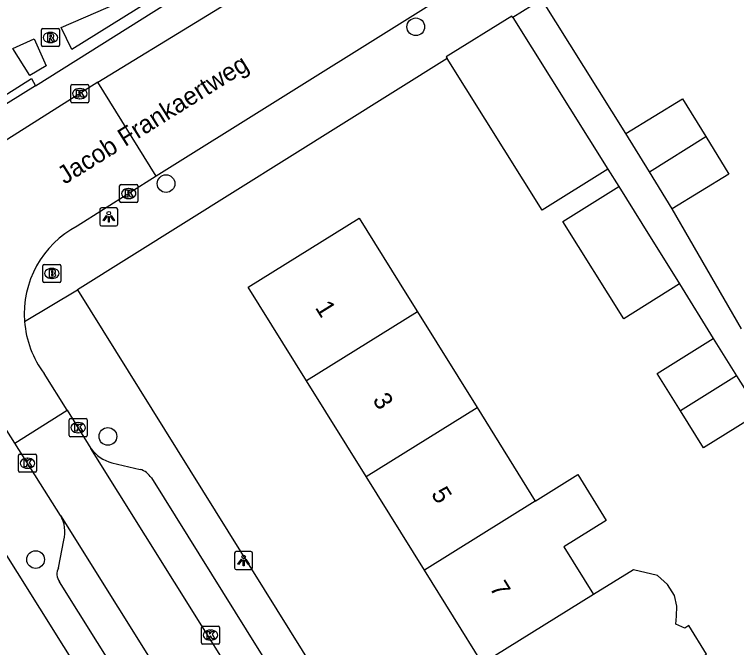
# Model space of a CAD drawing. Extents: x 159353 to 160616, y 385893 to 387321.
# Drawn here: x 159682.19 to 159722.15, y 386153.33 to 386188.38 of the extents above; entities that cross this region are included whole.
import ezdxf

# ---------------------------------------------------------------- set-up
doc = ezdxf.new("R2010")
doc.units = 0
for name, color, linetype in [('IMGEO_Boom', 7, 'Continuous'), ('IMGEO_Brandkraan', 7, 'Continuous'), ('IMGEO_Kolk', 7, 'Continuous'), ('IMGEO_Lichtpunt', 7, 'Continuous'), ('IMGEO_Openbare_ruimte_label', 7, 'Continuous'), ('IMGEO_Pand', 7, 'Continuous'), ('IMGEO_Pand_nummerreeks', 7, 'Continuous'), ('IMGEO_Rijbaan_lokaal_open', 7, 'Continuous'), ('IMGEO_Rioolput', 7, 'Continuous'), ('IMGEO_Voetpad_open', 7, 'Continuous')]:
    doc.layers.add(name, color=color, linetype=linetype)

msp = doc.modelspace()

# ---------------------------------------------------------------- linework, layer by layer
at = {"layer": 'IMGEO_Boom'}
for centre in [(159704.397, 386187.696), (159690.577, 386179.013), (159687.358, 386165.017), (159683.361, 386158.199)]:
    msp.add_circle(centre, 0.489, dxfattribs=at)
at = {"layer": 'IMGEO_Brandkraan'}
for p, q in [((159683.835, 386174.543), (159684.687, 386174.543)), ((159683.76, 386173.617), (159683.76, 386174.469)), ((159684.248, 386174.323), (159684.273, 386174.323)), ((159684.761, 386174.469), (159684.761, 386173.617)), ((159684.271, 386173.763), (159684.246, 386173.763)), ((159684.687, 386173.543), (159683.835, 386173.543))]:
    msp.add_line(p, q, dxfattribs=at)
for points in [[(159683.835, 386174.543), (159684.687, 386174.543)], [(159683.76, 386173.617), (159683.76, 386174.469)], [(159684.108, 386174.243), (159684.108, 386173.843), (159684.321, 386173.843)], [(159684.339, 386174.243), (159684.108, 386174.243)], [(159684.287, 386174.162), (159684.233, 386174.162), (159684.233, 386174.086)], [(159684.761, 386174.469), (159684.761, 386173.617)], [(159684.233, 386174.086), (159684.286, 386174.086)], [(159684.295, 386174.01), (159684.233, 386174.01), (159684.233, 386173.929)], [(159684.233, 386173.929), (159684.295, 386173.929)], [(159684.687, 386173.543), (159683.835, 386173.543)]]:
    msp.add_lwpolyline(points, dxfattribs=at)
for centre, radius, start, end in [((159683.837, 386174.467), 0.0765, 91.552, 178.448), ((159683.837, 386174.467), 0.0765, 91.552, 178.448), ((159684.685, 386174.467), 0.0765, 1.552, 88.448), ((159684.685, 386174.467), 0.0765, 1.552, 88.448), ((159684.288, 386174.124), 0.0379, 267.8285, 90.9355), ((159684.343, 386174.098), 0.145, 59.4692, 91.5367), ((159684.368, 386174.145), 0.0922, 285.5137, 58.1501), ((159684.296, 386173.969), 0.0404, 269.8759, 90.5077), ((159684.327, 386174.094), 0.251, 268.6676, 293.5347), ((159684.373, 386173.953), 0.105, 301.3115, 78.989), ((159683.837, 386173.619), 0.0765, 181.552, 268.448), ((159683.837, 386173.619), 0.0765, 181.552, 268.448), ((159684.685, 386173.619), 0.0765, 271.552, 358.448), ((159684.685, 386173.619), 0.0765, 271.552, 358.448)]:
    msp.add_arc(centre, radius, start, end, dxfattribs=at)
for centre, major_axis, ratio, start_param, end_param in [((159684.247, 386174.043), (-0.387, 0.002), 0.722429, 4.712389, 7.853982), ((159684.272, 386174.043), (-0.39, 0.002), 0.717154, 1.570796, 4.712389)]:
    msp.add_ellipse(centre, major_axis=major_axis, ratio=ratio, start_param=start_param, end_param=end_param, dxfattribs=at)
at = {"layer": 'IMGEO_Kolk'}
for p, q in [((159685.304, 386183.569), (159685.304, 386184.421)), ((159685.379, 386184.495), (159686.231, 386184.495)), ((159685.792, 386184.275), (159685.817, 386184.275)), ((159686.305, 386184.421), (159686.305, 386183.569)), ((159686.231, 386183.495), (159685.379, 386183.495)), ((159685.815, 386183.715), (159685.79, 386183.715)), ((159688.085, 386178.963), (159688.937, 386178.963)), ((159688.01, 386178.037), (159688.01, 386178.889)), ((159688.498, 386178.743), (159688.523, 386178.743)), ((159689.011, 386178.889), (159689.011, 386178.037)), ((159688.521, 386178.183), (159688.496, 386178.183)), ((159688.937, 386177.963), (159688.085, 386177.963)), ((159685.214, 386165.077), (159685.214, 386165.929)), ((159685.289, 386166.003), (159686.141, 386166.003)), ((159685.702, 386165.783), (159685.727, 386165.783)), ((159686.215, 386165.929), (159686.215, 386165.077)), ((159686.141, 386165.003), (159685.289, 386165.003)), ((159685.725, 386165.223), (159685.7, 386165.223)), ((159682.408, 386163.107), (159682.408, 386163.959)), ((159682.483, 386164.033), (159683.335, 386164.033)), ((159682.896, 386163.813), (159682.921, 386163.813)), ((159683.409, 386163.959), (159683.409, 386163.107)), ((159683.335, 386163.033), (159682.483, 386163.033)), ((159682.919, 386163.253), (159682.894, 386163.253)), ((159692.537, 386153.591), (159692.537, 386154.443)), ((159692.612, 386154.517), (159693.464, 386154.517)), ((159693.025, 386154.297), (159693.05, 386154.297)), ((159693.538, 386154.443), (159693.538, 386153.591)), ((159693.464, 386153.517), (159692.612, 386153.517)), ((159693.048, 386153.737), (159693.023, 386153.737))]:
    msp.add_line(p, q, dxfattribs=at)
for points in [[(159685.304, 386183.569), (159685.304, 386184.421)], [(159685.379, 386184.495), (159686.231, 386184.495)], [(159685.625, 386184.195), (159685.748, 386184.195), (159685.748, 386184.044), (159685.878, 386184.195), (159686.042, 386184.195), (159685.896, 386184.044), (159686.049, 386183.795), (159685.897, 386183.795), (159685.812, 386183.959), (159685.748, 386183.892), (159685.748, 386183.795), (159685.625, 386183.795), (159685.625, 386184.195)], [(159686.305, 386184.421), (159686.305, 386183.569)], [(159686.231, 386183.495), (159685.379, 386183.495)], [(159688.085, 386178.963), (159688.937, 386178.963)], [(159688.01, 386178.037), (159688.01, 386178.889)], [(159688.331, 386178.663), (159688.454, 386178.663), (159688.454, 386178.512), (159688.584, 386178.663), (159688.748, 386178.663), (159688.602, 386178.512), (159688.755, 386178.263), (159688.603, 386178.263), (159688.518, 386178.427), (159688.454, 386178.36), (159688.454, 386178.263), (159688.331, 386178.263), (159688.331, 386178.663)], [(159689.011, 386178.889), (159689.011, 386178.037)], [(159688.937, 386177.963), (159688.085, 386177.963)], [(159685.214, 386165.077), (159685.214, 386165.929)], [(159685.289, 386166.003), (159686.141, 386166.003)], [(159686.215, 386165.929), (159686.215, 386165.077)], [(159685.535, 386165.703), (159685.658, 386165.703), (159685.658, 386165.552), (159685.788, 386165.703), (159685.952, 386165.703), (159685.806, 386165.552), (159685.959, 386165.303), (159685.807, 386165.303), (159685.722, 386165.467), (159685.658, 386165.4), (159685.658, 386165.303), (159685.535, 386165.303), (159685.535, 386165.703)], [(159686.141, 386165.003), (159685.289, 386165.003)], [(159682.408, 386163.107), (159682.408, 386163.959)], [(159682.483, 386164.033), (159683.335, 386164.033)], [(159683.409, 386163.959), (159683.409, 386163.107)], [(159682.729, 386163.733), (159682.852, 386163.733), (159682.852, 386163.582), (159682.982, 386163.733), (159683.146, 386163.733), (159683, 386163.582), (159683.153, 386163.333), (159683.001, 386163.333), (159682.916, 386163.497), (159682.852, 386163.43), (159682.852, 386163.333), (159682.729, 386163.333), (159682.729, 386163.733)], [(159683.335, 386163.033), (159682.483, 386163.033)], [(159692.537, 386153.591), (159692.537, 386154.443)], [(159692.612, 386154.517), (159693.464, 386154.517)], [(159692.858, 386154.217), (159692.981, 386154.217), (159692.981, 386154.066), (159693.111, 386154.217), (159693.275, 386154.217), (159693.129, 386154.066), (159693.282, 386153.817), (159693.13, 386153.817), (159693.045, 386153.981), (159692.981, 386153.914), (159692.981, 386153.817), (159692.858, 386153.817), (159692.858, 386154.217)], [(159693.538, 386154.443), (159693.538, 386153.591)], [(159693.464, 386153.517), (159692.612, 386153.517)]]:
    msp.add_lwpolyline(points, dxfattribs=at)
for centre, start, end in [((159685.381, 386184.419), 91.552, 178.448), ((159685.381, 386184.419), 91.552, 178.448), ((159686.229, 386184.419), 1.552, 88.448), ((159686.229, 386184.419), 1.552, 88.448), ((159685.381, 386183.571), 181.552, 268.448), ((159685.381, 386183.571), 181.552, 268.448), ((159686.229, 386183.571), 271.552, 358.448), ((159686.229, 386183.571), 271.552, 358.448), ((159688.087, 386178.887), 91.552, 178.448), ((159688.087, 386178.887), 91.552, 178.448), ((159688.935, 386178.887), 1.552, 88.448), ((159688.935, 386178.887), 1.552, 88.448), ((159688.087, 386178.039), 181.552, 268.448), ((159688.087, 386178.039), 181.552, 268.448), ((159688.935, 386178.039), 271.552, 358.448), ((159688.935, 386178.039), 271.552, 358.448), ((159685.291, 386165.927), 91.552, 178.448), ((159685.291, 386165.927), 91.552, 178.448), ((159686.139, 386165.927), 1.552, 88.448), ((159686.139, 386165.927), 1.552, 88.448), ((159685.291, 386165.079), 181.552, 268.448), ((159685.291, 386165.079), 181.552, 268.448), ((159686.139, 386165.079), 271.552, 358.448), ((159686.139, 386165.079), 271.552, 358.448), ((159682.485, 386163.957), 91.552, 178.448), ((159682.485, 386163.957), 91.552, 178.448), ((159683.333, 386163.957), 1.552, 88.448), ((159683.333, 386163.957), 1.552, 88.448), ((159682.485, 386163.109), 181.552, 268.448), ((159682.485, 386163.109), 181.552, 268.448), ((159683.333, 386163.109), 271.552, 358.448), ((159683.333, 386163.109), 271.552, 358.448), ((159692.614, 386154.441), 91.552, 178.448), ((159692.614, 386154.441), 91.552, 178.448), ((159693.462, 386154.441), 1.552, 88.448), ((159693.462, 386154.441), 1.552, 88.448), ((159692.614, 386153.593), 181.552, 268.448), ((159692.614, 386153.593), 181.552, 268.448), ((159693.462, 386153.593), 271.552, 358.448), ((159693.462, 386153.593), 271.552, 358.448)]:
    msp.add_arc(centre, 0.0765, start, end, dxfattribs=at)
for centre, major_axis, ratio, start_param, end_param in [((159685.791, 386183.995), (-0.387, 0.002), 0.722429, 4.712389, 7.853982), ((159685.816, 386183.995), (-0.39, 0.002), 0.717154, 1.570796, 4.712389), ((159688.497, 386178.463), (-0.387, 0.002), 0.722429, 4.712389, 7.853982), ((159688.522, 386178.463), (-0.39, 0.002), 0.717154, 1.570796, 4.712389), ((159685.701, 386165.503), (-0.387, 0.002), 0.722429, 4.712389, 7.853982), ((159685.726, 386165.503), (-0.39, 0.002), 0.717154, 1.570796, 4.712389), ((159682.895, 386163.533), (-0.387, 0.002), 0.722429, 4.712389, 7.853982), ((159682.92, 386163.533), (-0.39, 0.002), 0.717154, 1.570796, 4.712389), ((159693.024, 386154.017), (-0.387, 0.002), 0.722429, 4.712389, 7.853982), ((159693.049, 386154.017), (-0.39, 0.002), 0.717154, 1.570796, 4.712389)]:
    msp.add_ellipse(centre, major_axis=major_axis, ratio=ratio, start_param=start_param, end_param=end_param, dxfattribs=at)
at = {"layer": 'IMGEO_Lichtpunt'}
for p, q in [((159686.91, 386177.579), (159686.91, 386176.772)), ((159686.91, 386177.579), (159686.91, 386176.772)), ((159687.812, 386177.674), (159687.004, 386177.674)), ((159687.812, 386177.674), (159687.004, 386177.674)), ((159687.906, 386176.772), (159687.906, 386177.579)), ((159687.906, 386176.772), (159687.906, 386177.579)), ((159687.004, 386176.678), (159687.812, 386176.678)), ((159687.004, 386176.678), (159687.812, 386176.678)), ((159694.37, 386158.55), (159694.37, 386157.743)), ((159694.37, 386158.55), (159694.37, 386157.743)), ((159695.272, 386158.645), (159694.464, 386158.645)), ((159695.272, 386158.645), (159694.464, 386158.645)), ((159695.366, 386157.743), (159695.366, 386158.55)), ((159695.366, 386157.743), (159695.366, 386158.55)), ((159694.464, 386157.649), (159695.272, 386157.649)), ((159694.464, 386157.649), (159695.272, 386157.649))]:
    msp.add_line(p, q, dxfattribs=at)
for points in [[(159687.284, 386177.243), (159687.323, 386177.215), (159687.135, 386176.953), (159687.097, 386176.98), (159687.284, 386177.243)], [(159687.386, 386177.195), (159687.433, 386177.195), (159687.433, 386176.873), (159687.386, 386176.873), (159687.386, 386177.195)], [(159687.496, 386177.215), (159687.534, 386177.242), (159687.721, 386176.98), (159687.682, 386176.952), (159687.496, 386177.215)], [(159694.744, 386158.214), (159694.783, 386158.186), (159694.595, 386157.924), (159694.557, 386157.951), (159694.744, 386158.214)], [(159694.846, 386158.166), (159694.893, 386158.166), (159694.893, 386157.844), (159694.846, 386157.844), (159694.846, 386158.166)], [(159694.956, 386158.186), (159694.994, 386158.213), (159695.181, 386157.951), (159695.142, 386157.923), (159694.956, 386158.186)]]:
    msp.add_lwpolyline(points, dxfattribs=at)
for centre in [(159687.409, 386177.377), (159694.869, 386158.348)]:
    msp.add_circle(centre, 0.0994, dxfattribs=at)
for centre, start, end in [((159687.004, 386177.579), 90, 180), ((159687.004, 386177.579), 90, 180), ((159687.812, 386177.579), 0, 90), ((159687.812, 386177.579), 0, 90), ((159687.004, 386176.772), 180, 270), ((159687.004, 386176.772), 180, 270), ((159687.812, 386176.772), 270, 0), ((159687.812, 386176.772), 270, 360), ((159694.464, 386158.55), 90, 180), ((159694.464, 386158.55), 90, 180), ((159695.272, 386158.55), 0, 90), ((159695.272, 386158.55), 0, 90), ((159694.464, 386157.743), 180, 270), ((159694.464, 386157.743), 180, 270), ((159695.272, 386157.743), 270, 0), ((159695.272, 386157.743), 270, 360)]:
    msp.add_arc(centre, 0.0946, start, end, dxfattribs=at)
at = {"layer": 'IMGEO_Pand'}
for points in [[(159709.758, 386188.216), (159709.709, 386188.295), (159706.086, 386186.026), (159706.136, 386185.947)], [(159709.758, 386188.216), (159715.021, 386179.818)], [(159715.021, 386179.818), (159711.398, 386177.548), (159706.136, 386185.947)], [(159716.018, 386181.79), (159719.157, 386183.716), (159720.439, 386181.626)], [(159717.321, 386179.665), (159716.018, 386181.79)], [(159717.321, 386179.665), (159720.439, 386181.626)], [(159720.439, 386181.626), (159721.721, 386179.537), (159718.582, 386177.611)], [(159718.582, 386177.611), (159717.321, 386179.665)], [(159718.998, 386173.467), (159715.904, 386171.529), (159712.527, 386176.922), (159715.626, 386178.852)], [(159715.626, 386178.852), (159716.909, 386176.803), (159718.998, 386173.467)], [(159698.354, 386168.096), (159695.125, 386173.284), (159701.262, 386177.103), (159703.904, 386172.858), (159704.49, 386171.917)], [(159704.49, 386171.917), (159698.354, 386168.096)], [(159704.49, 386171.917), (159707.785, 386166.62)], [(159719.037, 386166.44), (159717.751, 386168.494), (159720.853, 386170.438)], [(159720.853, 386170.438), (159722.145, 386168.375)], [(159722.145, 386168.375), (159719.037, 386166.44)], [(159722.145, 386168.375), (159723.428, 386166.327)], [(159701.649, 386162.8), (159698.354, 386168.096)], [(159701.649, 386162.8), (159707.785, 386166.62)], [(159707.785, 386166.62), (159711.009, 386161.441)], [(159723.428, 386166.327), (159720.325, 386164.383), (159719.037, 386166.44)], [(159704.872, 386157.62), (159701.649, 386162.8)], [(159711.009, 386161.441), (159713.358, 386162.901), (159714.936, 386160.364), (159712.587, 386158.904), (159714.231, 386156.262)], [(159711.009, 386161.441), (159704.872, 386157.62)], [(159708.095, 386152.441), (159704.872, 386157.62)], [(159717.46, 386151.087), (159720.485, 386152.968), (159719.504, 386154.545), (159719.276, 386154.403), (159718.78, 386154.627), (159718.826, 386155.061), (159718.837, 386155.626), (159718.704, 386156.203), (159718.327, 386156.824), (159717.774, 386157.324), (159716.439, 386157.635), (159714.231, 386156.262)], [(159714.231, 386156.262), (159708.095, 386152.441)]]:
    msp.add_lwpolyline(points, dxfattribs=at)
at = {"layer": 'IMGEO_Rijbaan_lokaal_open'}
for points in [[(159710.076, 386191.982), (159690.037, 386179.433)], [(159686.801, 386184.624), (159698.284, 386191.67)], [(159686.801, 386184.624), (159667.269, 386172.261)], [(159690.037, 386179.433), (159686.801, 386184.624)], [(159690.037, 386179.433), (159685.663, 386176.667)], [(159685.102, 386166.476), (159683.833, 386168.497)], [(159682.211, 386164.651), (159680.899, 386166.685)], [(159682.211, 386164.651), (159685.102, 386166.476)], [(159685.102, 386166.476), (159686.42, 386164.358)], [(159684.734, 386160.648), (159682.211, 386164.651)], [(159732.063, 386091.102), (159713.32, 386121.238), (159712.101, 386123.199), (159706.934, 386131.508), (159705.576, 386133.684), (159700.717, 386141.456), (159699.735, 386143.025), (159695.462, 386149.864), (159694.078, 386152.113), (159686.42, 386164.358)], [(159684.734, 386160.648), (159729.424, 386089.133)]]:
    msp.add_lwpolyline(points, dxfattribs=at)
for centre, radius, start, end in [((159688.233, 386171.802), 5.502, 117.8495, 184.3567), ((159688.244, 386171.804), 5.513, 184.371, 216.8585)]:
    msp.add_arc(centre, radius, start, end, dxfattribs=at)
at = {"layer": 'IMGEO_Rioolput'}
for p, q in [((159683.679, 386186.678), (159683.679, 386187.53)), ((159683.754, 386187.604), (159684.606, 386187.604)), ((159684.167, 386187.384), (159684.192, 386187.384)), ((159684.68, 386187.53), (159684.68, 386186.678)), ((159684.606, 386186.604), (159683.754, 386186.604)), ((159684.19, 386186.824), (159684.165, 386186.824))]:
    msp.add_line(p, q, dxfattribs=at)
for points in [[(159683.679, 386186.678), (159683.679, 386187.53)], [(159683.754, 386187.604), (159684.606, 386187.604)], [(159684.68, 386187.53), (159684.68, 386186.678)], [(159684.268, 386187.302), (159684.016, 386187.304), (159684.016, 386186.904)], [(159684.016, 386186.904), (159684.14, 386186.904), (159684.14, 386187.066), (159684.151, 386187.066)], [(159684.194, 386187.223), (159684.14, 386187.223), (159684.14, 386187.142)], [(159684.14, 386187.142), (159684.192, 386187.142)], [(159684.198, 386187.037), (159684.269, 386186.904), (159684.409, 386186.904), (159684.344, 386187.03)], [(159684.606, 386186.604), (159683.754, 386186.604)]]:
    msp.add_lwpolyline(points, dxfattribs=at)
for centre, radius, start, end in [((159683.756, 386187.528), 0.0765, 91.552, 178.448), ((159683.756, 386187.528), 0.0765, 91.552, 178.448), ((159684.604, 386187.528), 0.0765, 1.552, 88.448), ((159684.604, 386187.528), 0.0765, 1.552, 88.448), ((159684.15, 386187.013), 0.0533, 26.0293, 88.6989), ((159684.176, 386187.331), 0.19, 274.7715, 282.9687), ((159684.2, 386187.127), 0.0964, 77.0061, 93.1865), ((159684.214, 386187.184), 0.0378, 276.6634, 79.6772), ((159684.267, 386187.192), 0.109, 350.3612, 89.416), ((159684.265, 386187.192), 0.112, 277.5842, 350.9817), ((159684.249, 386186.977), 0.108, 29.5134, 73.7905), ((159683.756, 386186.68), 0.0765, 181.552, 268.448), ((159683.756, 386186.68), 0.0765, 181.552, 268.448), ((159684.604, 386186.68), 0.0765, 271.552, 358.448), ((159684.604, 386186.68), 0.0765, 271.552, 358.448)]:
    msp.add_arc(centre, radius, start, end, dxfattribs=at)
for centre, major_axis, ratio, start_param, end_param in [((159684.166, 386187.104), (-0.387, 0.002), 0.722429, 4.712389, 7.853982), ((159684.191, 386187.104), (-0.39, 0.002), 0.717154, 1.570796, 4.712389)]:
    msp.add_ellipse(centre, major_axis=major_axis, ratio=ratio, start_param=start_param, end_param=end_param, dxfattribs=at)
at = {"layer": 'IMGEO_Voetpad_open'}
for points in [[(159692.137, 386189.957), (159691.793, 386190.467), (159685.357, 386186.443), (159684.781, 386187.668), (159691.207, 386190.458), (159698.352, 386193.525), (159698.969, 386192.653)], [(159683.351, 386184.43), (159692.137, 386189.957)], [(159711.363, 386189.221), (159709.758, 386188.216)], [(159716.018, 386181.79), (159711.363, 386189.221)], [(159682.099, 386186.503), (159683.271, 386187.026), (159683.947, 386185.537), (159683.047, 386185.008), (159682.099, 386186.503)], [(159706.136, 386185.947), (159685.685, 386173.135)], [(159679.947, 386182.816), (159683.126, 386184.832), (159683.351, 386184.43)], [(159683.351, 386184.43), (159680.171, 386182.463)], [(159715.021, 386179.818), (159715.626, 386178.852)], [(159722.427, 386170.969), (159718.582, 386177.611)], [(159718.998, 386173.467), (159720.853, 386170.438)], [(159682.747, 386171.384), (159685.685, 386173.135)], [(159685.685, 386173.135), (159722.272, 386114.357)], [(159712.934, 386108.61), (159677.208, 386165.677), (159674.448, 386166.054)], [(159687.581, 386163.56), (159689.145, 386163.195)], [(159689.763, 386162.72), (159695.716, 386153.19), (159697.136, 386150.917), (159701.414, 386144.069), (159702.412, 386142.47), (159707.231, 386134.755), (159708.615, 386132.541), (159713.768, 386124.242), (159714.974, 386122.307), (159718.917, 386115.978)], [(159684.627, 386157.743), (159684.921, 386159.27)], [(159692.745, 386144.645), (159692.133, 386145.07), (159684.676, 386156.971)]]:
    msp.add_lwpolyline(points, dxfattribs=at)
for centre, radius, start, end in [((159688.078, 386165.527), 2.029, 215.182, 255.8135), ((159688.824, 386162.138), 1.105, 31.8038, 73.1038), ((159683.196, 386159.738), 1.787, 344.835, 30.6211), ((159685.27, 386157.396), 0.731, 151.6824, 215.5811)]:
    msp.add_arc(centre, radius, start, end, dxfattribs=at)

# ---------------------------------------------------------------- texts
at = {"layer": 'IMGEO_Openbare_ruimte_label'}
msp.add_text('Jacob Frankaertweg', height=1, rotation=32.0054, dxfattribs=at).set_placement((159684.967, 386178.945))
at = {"layer": 'IMGEO_Pand_nummerreeks'}
for s, p in [('1', (159698.799, 386172.15)), ('3', (159701.978, 386167.042)), ('5', (159705.216, 386161.837)), ('7', (159708.455, 386156.632))]:
    msp.add_text(s, height=1, rotation=301.8931, dxfattribs=at).set_placement(p)

doc.saveas('drawing.dxf')
